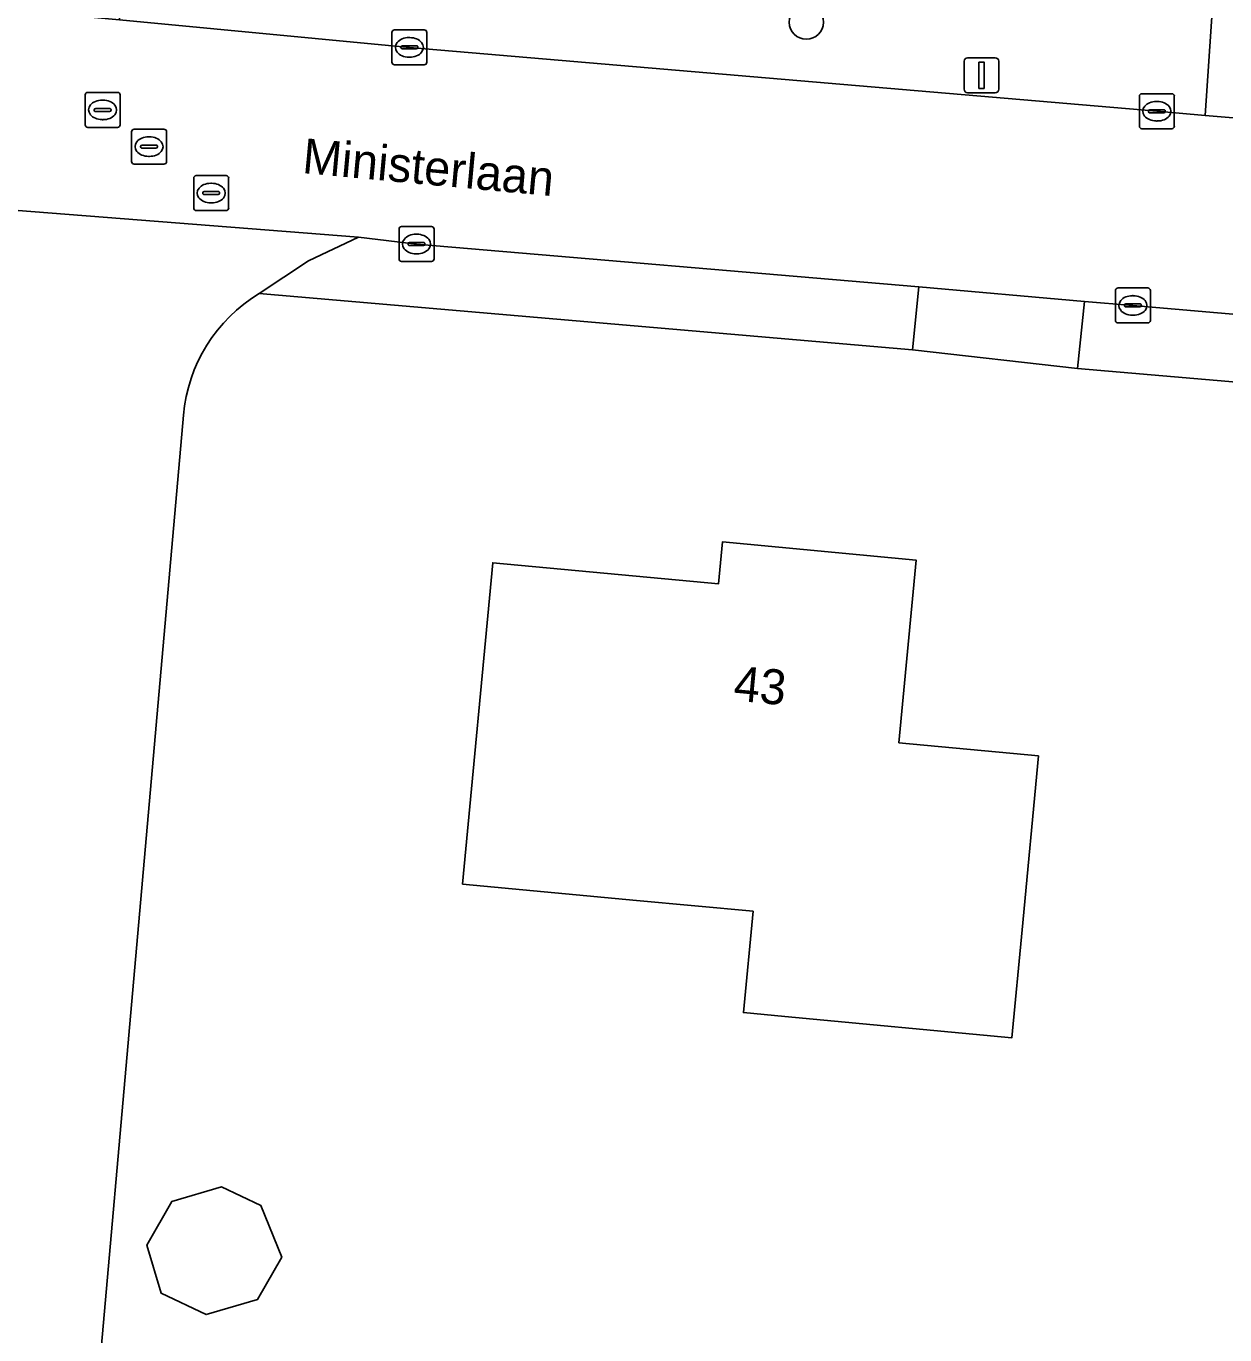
# Model space of a CAD drawing. Extents: x 162722 to 165104, y 384719 to 386284.
# Drawn here: x 163950.36 to 163984.67, y 385149.88 to 385187.32 of the extents above; entities that cross this region are included whole.
import ezdxf

# ---------------------------------------------------------------- set-up
doc = ezdxf.new("R2010")
doc.units = 0
for name, color, linetype in [('IMGEO_Boom', 7, 'Continuous'), ('IMGEO_Erf', 7, 'Continuous'), ('IMGEO_Groenvoorziening', 7, 'Continuous'), ('IMGEO_Kolk', 7, 'Continuous'), ('IMGEO_Lichtmast', 7, 'Continuous'), ('IMGEO_Openbare_ruimte_label', 7, 'Continuous'), ('IMGEO_Pand', 7, 'Continuous'), ('IMGEO_Pand_nummerreeks', 7, 'Continuous'), ('IMGEO_Parkeervlak_open', 7, 'Continuous'), ('IMGEO_Rijbaan_lokaal_gesloten', 7, 'Continuous'), ('IMGEO_Rioolput', 7, 'Continuous'), ('IMGEO_Voetpad_open', 7, 'Continuous')]:
    doc.layers.add(name, color=color, linetype=linetype)

msp = doc.modelspace()

# ---------------------------------------------------------------- linework, layer by layer
at = {"layer": 'IMGEO_Boom'}
msp.add_circle((163972.695, 385187.431), 0.489, dxfattribs=at)
at = {"layer": 'IMGEO_Erf'}
for points in [[(164019.273, 385173.042), (164011.601, 385174.616), (164006.685, 385175.256), (164000.92, 385175.782), (164000, 385175.844), (163980.454, 385177.525), (163975.738, 385178.054), (163957.036, 385179.674)], [(163954.865, 385176.188), (163950.926, 385131.52)]]:
    msp.add_lwpolyline(points, dxfattribs=at)
for points in [[(163972.078, 385158.986), (163970.896, 385159.097), (163971.169, 385161.996), (163967.834, 385162.308), (163962.855, 385162.774), (163963.717, 385171.965), (163970.18, 385171.359), (163970.293, 385172.563), (163975.835, 385172.044), (163975.345, 385166.815), (163979.338, 385166.441), (163978.871, 385161.463), (163978.582, 385158.376)], [(163956.986, 385150.891), (163955.512, 385150.455), (163954.223, 385151.068), (163953.819, 385152.447), (163954.532, 385153.694), (163955.951, 385154.113), (163957.084, 385153.575), (163957.679, 385152.102)]]:
    msp.add_lwpolyline(points, close=True, dxfattribs=at)
msp.add_arc((163959.38, 385175.795), 4.532, 121.1461, 175.0265, dxfattribs=at)
at = {"layer": 'IMGEO_Groenvoorziening'}
msp.add_lwpolyline([(163984.32, 385187.873), (163953.324, 385190.647), (163953.03, 385187.504), (163961.332, 385186.712), (163982.729, 385184.885), (163984.115, 385184.765)], close=True, dxfattribs=at)
at = {"layer": 'IMGEO_Kolk'}
for p, q in [((163960.831, 385186.286), (163960.831, 385187.138)), ((163960.906, 385187.212), (163961.758, 385187.212)), ((163961.319, 385186.992), (163961.344, 385186.992)), ((163961.832, 385187.138), (163961.832, 385186.286)), ((163961.09, 385186.706), (163961.09, 385186.718)), ((163961.528, 385186.669), (163961.13, 385186.669)), ((163961.133, 385186.755), (163961.531, 385186.755)), ((163961.574, 385186.718), (163961.574, 385186.706)), ((163961.342, 385186.432), (163961.317, 385186.432)), ((163961.758, 385186.212), (163960.906, 385186.212)), ((163982.228, 385184.459), (163982.228, 385185.311)), ((163982.303, 385185.385), (163983.155, 385185.385)), ((163982.716, 385185.165), (163982.741, 385185.165)), ((163983.229, 385185.311), (163983.229, 385184.459)), ((163982.487, 385184.879), (163982.487, 385184.891)), ((163982.925, 385184.842), (163982.527, 385184.842)), ((163982.53, 385184.928), (163982.928, 385184.928)), ((163982.971, 385184.891), (163982.971, 385184.879)), ((163983.155, 385184.385), (163982.303, 385184.385)), ((163982.739, 385184.605), (163982.714, 385184.605)), ((163961.036, 385180.66), (163961.036, 385181.512)), ((163961.111, 385181.586), (163961.963, 385181.586)), ((163961.524, 385181.366), (163961.549, 385181.366)), ((163962.037, 385181.512), (163962.037, 385180.66)), ((163961.295, 385181.08), (163961.295, 385181.092)), ((163961.733, 385181.043), (163961.335, 385181.043)), ((163961.338, 385181.129), (163961.736, 385181.129)), ((163961.779, 385181.092), (163961.779, 385181.08)), ((163961.547, 385180.806), (163961.522, 385180.806)), ((163961.963, 385180.586), (163961.111, 385180.586)), ((163981.542, 385178.902), (163981.542, 385179.754)), ((163981.617, 385179.828), (163982.469, 385179.828)), ((163982.03, 385179.608), (163982.055, 385179.608)), ((163982.543, 385179.754), (163982.543, 385178.902)), ((163981.801, 385179.322), (163981.801, 385179.334)), ((163982.239, 385179.285), (163981.841, 385179.285)), ((163981.844, 385179.371), (163982.242, 385179.371)), ((163982.285, 385179.334), (163982.285, 385179.322)), ((163982.469, 385178.828), (163981.617, 385178.828)), ((163982.053, 385179.048), (163982.028, 385179.048))]:
    msp.add_line(p, q, dxfattribs=at)
for points in [[(163960.831, 385186.286), (163960.831, 385187.138)], [(163960.906, 385187.212), (163961.758, 385187.212)], [(163961.832, 385187.138), (163961.832, 385186.286)], [(163961.758, 385186.212), (163960.906, 385186.212)], [(163982.228, 385184.459), (163982.228, 385185.311)], [(163982.303, 385185.385), (163983.155, 385185.385)], [(163983.229, 385185.311), (163983.229, 385184.459)], [(163983.155, 385184.385), (163982.303, 385184.385)], [(163961.036, 385180.66), (163961.036, 385181.512)], [(163961.111, 385181.586), (163961.963, 385181.586)], [(163962.037, 385181.512), (163962.037, 385180.66)], [(163961.963, 385180.586), (163961.111, 385180.586)], [(163981.542, 385178.902), (163981.542, 385179.754)], [(163981.617, 385179.828), (163982.469, 385179.828)], [(163982.543, 385179.754), (163982.543, 385178.902)], [(163982.469, 385178.828), (163981.617, 385178.828)]]:
    msp.add_lwpolyline(points, dxfattribs=at)
for centre, radius, start, end in [((163960.908, 385187.136), 0.0765, 91.552, 178.448), ((163960.908, 385187.136), 0.0765, 91.552, 178.448), ((163961.756, 385187.136), 0.0765, 1.552, 88.448), ((163961.756, 385187.136), 0.0765, 1.552, 88.448), ((163961.13, 385186.715), 0.0403, 85.8775, 175.7526), ((163961.127, 385186.705), 0.0366, 178.938, 274.7102), ((163961.531, 385186.712), 0.043, 264.8664, 352.4533), ((163961.535, 385186.717), 0.0386, 1.7309, 96.639), ((163960.908, 385186.288), 0.0765, 181.552, 268.448), ((163960.908, 385186.288), 0.0765, 181.552, 268.448), ((163961.756, 385186.288), 0.0765, 271.552, 358.448), ((163961.756, 385186.288), 0.0765, 271.552, 358.448), ((163982.305, 385185.309), 0.0765, 91.552, 178.448), ((163982.305, 385185.309), 0.0765, 91.552, 178.448), ((163983.153, 385185.309), 0.0765, 1.552, 88.448), ((163983.153, 385185.309), 0.0765, 1.552, 88.448), ((163982.527, 385184.888), 0.0403, 85.8775, 175.7526), ((163982.524, 385184.878), 0.0366, 178.938, 274.7102), ((163982.928, 385184.885), 0.043, 264.8664, 352.4533), ((163982.932, 385184.89), 0.0386, 1.7309, 96.639), ((163982.305, 385184.461), 0.0765, 181.552, 268.448), ((163982.305, 385184.461), 0.0765, 181.552, 268.448), ((163983.153, 385184.461), 0.0765, 271.552, 358.448), ((163983.153, 385184.461), 0.0765, 271.552, 358.448), ((163961.113, 385181.51), 0.0765, 91.552, 178.448), ((163961.113, 385181.51), 0.0765, 91.552, 178.448), ((163961.961, 385181.51), 0.0765, 1.552, 88.448), ((163961.961, 385181.51), 0.0765, 1.552, 88.448), ((163961.335, 385181.089), 0.0403, 85.8775, 175.7526), ((163961.332, 385181.079), 0.0366, 178.938, 274.7102), ((163961.736, 385181.086), 0.043, 264.8664, 352.4533), ((163961.74, 385181.091), 0.0386, 1.7309, 96.639), ((163961.113, 385180.662), 0.0765, 181.552, 268.448), ((163961.113, 385180.662), 0.0765, 181.552, 268.448), ((163961.961, 385180.662), 0.0765, 271.552, 358.448), ((163961.961, 385180.662), 0.0765, 271.552, 358.448), ((163981.619, 385179.752), 0.0765, 91.552, 178.448), ((163981.619, 385179.752), 0.0765, 91.552, 178.448), ((163982.467, 385179.752), 0.0765, 1.552, 88.448), ((163982.467, 385179.752), 0.0765, 1.552, 88.448), ((163981.841, 385179.331), 0.0403, 85.8775, 175.7526), ((163981.838, 385179.321), 0.0366, 178.938, 274.7102), ((163982.242, 385179.328), 0.043, 264.8664, 352.4533), ((163982.246, 385179.333), 0.0386, 1.7309, 96.639), ((163981.619, 385178.904), 0.0765, 181.552, 268.448), ((163981.619, 385178.904), 0.0765, 181.552, 268.448), ((163982.467, 385178.904), 0.0765, 271.552, 358.448), ((163982.467, 385178.904), 0.0765, 271.552, 358.448)]:
    msp.add_arc(centre, radius, start, end, dxfattribs=at)
for centre, major_axis, ratio, start_param, end_param in [((163961.318, 385186.712), (-0.387, 0.002), 0.722429, 4.712389, 7.853982), ((163961.343, 385186.712), (-0.39, 0.002), 0.717154, 1.570796, 4.712389), ((163982.715, 385184.885), (-0.387, 0.002), 0.722429, 4.712389, 7.853982), ((163982.74, 385184.885), (-0.39, 0.002), 0.717154, 1.570796, 4.712389), ((163961.523, 385181.086), (-0.387, 0.002), 0.722429, 4.712389, 7.853982), ((163961.548, 385181.086), (-0.39, 0.002), 0.717154, 1.570796, 4.712389), ((163982.029, 385179.328), (-0.387, 0.002), 0.722429, 4.712389, 7.853982), ((163982.054, 385179.328), (-0.39, 0.002), 0.717154, 1.570796, 4.712389)]:
    msp.add_ellipse(centre, major_axis=major_axis, ratio=ratio, start_param=start_param, end_param=end_param, dxfattribs=at)
at = {"layer": 'IMGEO_Lichtmast'}
for p, q in [((163977.213, 385185.514), (163977.213, 385186.314)), ((163977.213, 385186.314), (163977.213, 385185.514)), ((163977.313, 385186.414), (163978.103, 385186.414)), ((163978.103, 385186.414), (163977.313, 385186.414)), ((163978.203, 385186.314), (163978.203, 385185.514)), ((163978.203, 385185.514), (163978.203, 385186.314)), ((163978.103, 385185.414), (163977.313, 385185.414)), ((163977.313, 385185.414), (163978.103, 385185.414))]:
    msp.add_line(p, q, dxfattribs=at)
msp.add_lwpolyline([(163977.633, 385186.289), (163977.783, 385186.289), (163977.783, 385185.539), (163977.633, 385185.539), (163977.633, 385186.289)], dxfattribs=at)
for centre, start, end in [((163977.313, 385186.314), 90, 180), ((163977.313, 385186.314), 90, 180), ((163978.103, 385186.314), 0, 90), ((163978.103, 385186.314), 360, 90), ((163977.313, 385185.514), 180, 270), ((163977.313, 385185.514), 180, 270), ((163978.103, 385185.514), 270, 0), ((163978.103, 385185.514), 270, 0)]:
    msp.add_arc(centre, 0.1, start, end, dxfattribs=at)
at = {"layer": 'IMGEO_Pand'}
for points in [[(163967.834, 385162.308), (163971.169, 385161.996), (163970.896, 385159.097), (163972.078, 385158.986), (163978.582, 385158.376), (163978.871, 385161.463), (163979.338, 385166.441), (163975.345, 385166.815), (163975.835, 385172.044), (163970.293, 385172.563), (163970.18, 385171.359), (163963.717, 385171.965), (163962.855, 385162.774)], [(163953.819, 385152.447), (163954.223, 385151.068), (163955.512, 385150.455), (163956.986, 385150.891), (163957.679, 385152.102), (163957.084, 385153.575), (163955.951, 385154.113), (163954.532, 385153.694)]]:
    msp.add_lwpolyline(points, close=True, dxfattribs=at)
at = {"layer": 'IMGEO_Parkeervlak_open'}
for points in [[(163961.537, 385181.086), (163959.871, 385181.283), (163958.444, 385180.6), (163957.036, 385179.674), (163975.738, 385178.054), (163975.917, 385179.858)], [(163980.454, 385177.525), (164000, 385175.844), (164000.92, 385175.782), (164001.089, 385177.667), (164000, 385177.774), (163982.043, 385179.328), (163980.657, 385179.445)]]:
    msp.add_lwpolyline(points, close=True, dxfattribs=at)
at = {"layer": 'IMGEO_Rijbaan_lokaal_gesloten'}
for points in [[(164069.537, 385160.271), (164053.648, 385167.548), (164050.878, 385168.812), (164049.034, 385169.655), (164038.924, 385174.279), (164037.91, 385174.757), (164034.061, 385176.359), (164024.328, 385179.48), (164014.356, 385181.719), (164009.373, 385182.493), (164006.361, 385182.82), (164004.157, 385183.013), (164002.022, 385183.193), (164000, 385183.379), (163997.041, 385183.651), (163985.03, 385184.687), (163984.115, 385184.765), (163982.729, 385184.885), (163961.332, 385186.712), (163953.03, 385187.504), (163948.264, 385187.936), (163942.935, 385188.388), (163927.518, 385189.855), (163916.96, 385190.797)], [(163957.036, 385179.674), (163958.444, 385180.6), (163959.871, 385181.283), (163946.345, 385182.337)], [(163946.345, 385182.337), (163959.871, 385181.283), (163961.537, 385181.086), (163975.917, 385179.858), (163980.657, 385179.445), (163982.043, 385179.328), (164000, 385177.774), (164001.089, 385177.667), (164003.306, 385177.464), (164006.878, 385177.162), (164011.653, 385176.534), (164019.703, 385174.889), (164019.892, 385174.859), (164021.592, 385174.502), (164023.254, 385173.995), (164026.265, 385173.125), (164031.751, 385171.269), (164036.795, 385169.137), (164051.9, 385162.23), (164052.042, 385162.153), (164054.177, 385161.165), (164066.085, 385155.714)], [(163950.926, 385131.52), (163954.865, 385176.188)]]:
    msp.add_lwpolyline(points, dxfattribs=at)
msp.add_arc((163959.38, 385175.795), 4.532, 121.1461, 175.0265, dxfattribs=at)
at = {"layer": 'IMGEO_Rioolput'}
for p, q in [((163952.051, 385184.497), (163952.051, 385185.349)), ((163952.126, 385185.423), (163952.978, 385185.423)), ((163952.539, 385185.203), (163952.564, 385185.203)), ((163953.052, 385185.349), (163953.052, 385184.497)), ((163952.31, 385184.917), (163952.31, 385184.929)), ((163952.748, 385184.88), (163952.35, 385184.88)), ((163952.353, 385184.966), (163952.751, 385184.966)), ((163952.794, 385184.929), (163952.794, 385184.917)), ((163952.978, 385184.423), (163952.126, 385184.423)), ((163952.562, 385184.643), (163952.537, 385184.643)), ((163953.455, 385184.372), (163954.307, 385184.372)), ((163953.38, 385183.446), (163953.38, 385184.298)), ((163953.868, 385184.152), (163953.893, 385184.152)), ((163954.381, 385184.298), (163954.381, 385183.446)), ((163953.639, 385183.866), (163953.639, 385183.878)), ((163954.077, 385183.829), (163953.679, 385183.829)), ((163953.682, 385183.915), (163954.08, 385183.915)), ((163954.123, 385183.878), (163954.123, 385183.866)), ((163954.307, 385183.372), (163953.455, 385183.372)), ((163953.891, 385183.592), (163953.866, 385183.592)), ((163955.158, 385182.117), (163955.158, 385182.969)), ((163955.233, 385183.043), (163956.085, 385183.043)), ((163956.159, 385182.969), (163956.159, 385182.117)), ((163955.417, 385182.537), (163955.417, 385182.549)), ((163955.855, 385182.5), (163955.457, 385182.5)), ((163955.46, 385182.586), (163955.858, 385182.586)), ((163955.646, 385182.823), (163955.671, 385182.823)), ((163955.901, 385182.549), (163955.901, 385182.537)), ((163955.669, 385182.263), (163955.644, 385182.263)), ((163956.085, 385182.043), (163955.233, 385182.043))]:
    msp.add_line(p, q, dxfattribs=at)
for points in [[(163952.051, 385184.497), (163952.051, 385185.349)], [(163952.126, 385185.423), (163952.978, 385185.423)], [(163953.052, 385185.349), (163953.052, 385184.497)], [(163952.978, 385184.423), (163952.126, 385184.423)], [(163953.455, 385184.372), (163954.307, 385184.372)], [(163953.38, 385183.446), (163953.38, 385184.298)], [(163954.381, 385184.298), (163954.381, 385183.446)], [(163954.307, 385183.372), (163953.455, 385183.372)], [(163955.158, 385182.117), (163955.158, 385182.969)], [(163955.233, 385183.043), (163956.085, 385183.043)], [(163956.159, 385182.969), (163956.159, 385182.117)], [(163956.085, 385182.043), (163955.233, 385182.043)]]:
    msp.add_lwpolyline(points, dxfattribs=at)
for centre, radius, start, end in [((163952.128, 385185.347), 0.0765, 91.552, 178.448), ((163952.128, 385185.347), 0.0765, 91.552, 178.448), ((163952.976, 385185.347), 0.0765, 1.552, 88.448), ((163952.976, 385185.347), 0.0765, 1.552, 88.448), ((163952.35, 385184.926), 0.0403, 85.8775, 175.7526), ((163952.347, 385184.916), 0.0366, 178.938, 274.7102), ((163952.751, 385184.923), 0.043, 264.8664, 352.4533), ((163952.755, 385184.928), 0.0386, 1.7309, 96.639), ((163952.128, 385184.499), 0.0765, 181.552, 268.448), ((163952.128, 385184.499), 0.0765, 181.552, 268.448), ((163952.976, 385184.499), 0.0765, 271.552, 358.448), ((163952.976, 385184.499), 0.0765, 271.552, 358.448), ((163953.457, 385184.296), 0.0765, 91.552, 178.448), ((163953.457, 385184.296), 0.0765, 91.552, 178.448), ((163954.305, 385184.296), 0.0765, 1.552, 88.448), ((163954.305, 385184.296), 0.0765, 1.552, 88.448), ((163953.679, 385183.875), 0.0403, 85.8775, 175.7526), ((163953.676, 385183.865), 0.0366, 178.938, 274.7102), ((163954.08, 385183.872), 0.043, 264.8664, 352.4533), ((163954.084, 385183.877), 0.0386, 1.7309, 96.639), ((163953.457, 385183.448), 0.0765, 181.552, 268.448), ((163953.457, 385183.448), 0.0765, 181.552, 268.448), ((163954.305, 385183.448), 0.0765, 271.552, 358.448), ((163954.305, 385183.448), 0.0765, 271.552, 358.448), ((163955.235, 385182.967), 0.0765, 91.552, 178.448), ((163955.235, 385182.967), 0.0765, 91.552, 178.448), ((163956.083, 385182.967), 0.0765, 1.552, 88.448), ((163956.083, 385182.967), 0.0765, 1.552, 88.448), ((163955.457, 385182.546), 0.0403, 85.8775, 175.7526), ((163955.454, 385182.536), 0.0366, 178.938, 274.7102), ((163955.858, 385182.543), 0.043, 264.8664, 352.4533), ((163955.862, 385182.548), 0.0386, 1.7309, 96.639), ((163955.235, 385182.119), 0.0765, 181.552, 268.448), ((163955.235, 385182.119), 0.0765, 181.552, 268.448), ((163956.083, 385182.119), 0.0765, 271.552, 358.448), ((163956.083, 385182.119), 0.0765, 271.552, 358.448)]:
    msp.add_arc(centre, radius, start, end, dxfattribs=at)
for centre, major_axis, ratio, start_param, end_param in [((163952.538, 385184.923), (-0.387, 0.002), 0.722429, 4.712389, 7.853982), ((163952.563, 385184.923), (-0.39, 0.002), 0.717154, 1.570796, 4.712389), ((163953.867, 385183.872), (-0.387, 0.002), 0.722429, 4.712389, 7.853982), ((163953.892, 385183.872), (-0.39, 0.002), 0.717154, 1.570796, 4.712389), ((163955.645, 385182.543), (-0.387, 0.002), 0.722429, 4.712389, 7.853982), ((163955.67, 385182.543), (-0.39, 0.002), 0.717154, 1.570796, 4.712389)]:
    msp.add_ellipse(centre, major_axis=major_axis, ratio=ratio, start_param=start_param, end_param=end_param, dxfattribs=at)
at = {"layer": 'IMGEO_Voetpad_open'}
for points in [[(163997.313, 385186.71), (163997.498, 385188.685), (163953.489, 385192.612), (163953.324, 385190.647), (163984.32, 385187.873), (163984.115, 385184.765), (163985.03, 385184.687), (163985.32, 385187.783)], [(163975.738, 385178.054), (163980.454, 385177.525), (163980.657, 385179.445), (163975.917, 385179.858)]]:
    msp.add_lwpolyline(points, close=True, dxfattribs=at)

# ---------------------------------------------------------------- texts
at = {"layer": 'IMGEO_Openbare_ruimte_label'}
msp.add_text('Ministerlaan', height=1, rotation=354.7226, dxfattribs=at).set_placement((163958.245, 385183.118))
at = {"layer": 'IMGEO_Pand_nummerreeks'}
msp.add_text('43', height=1, rotation=354.6433, dxfattribs=at).set_placement((163970.588, 385168.027))

doc.saveas('drawing.dxf')
